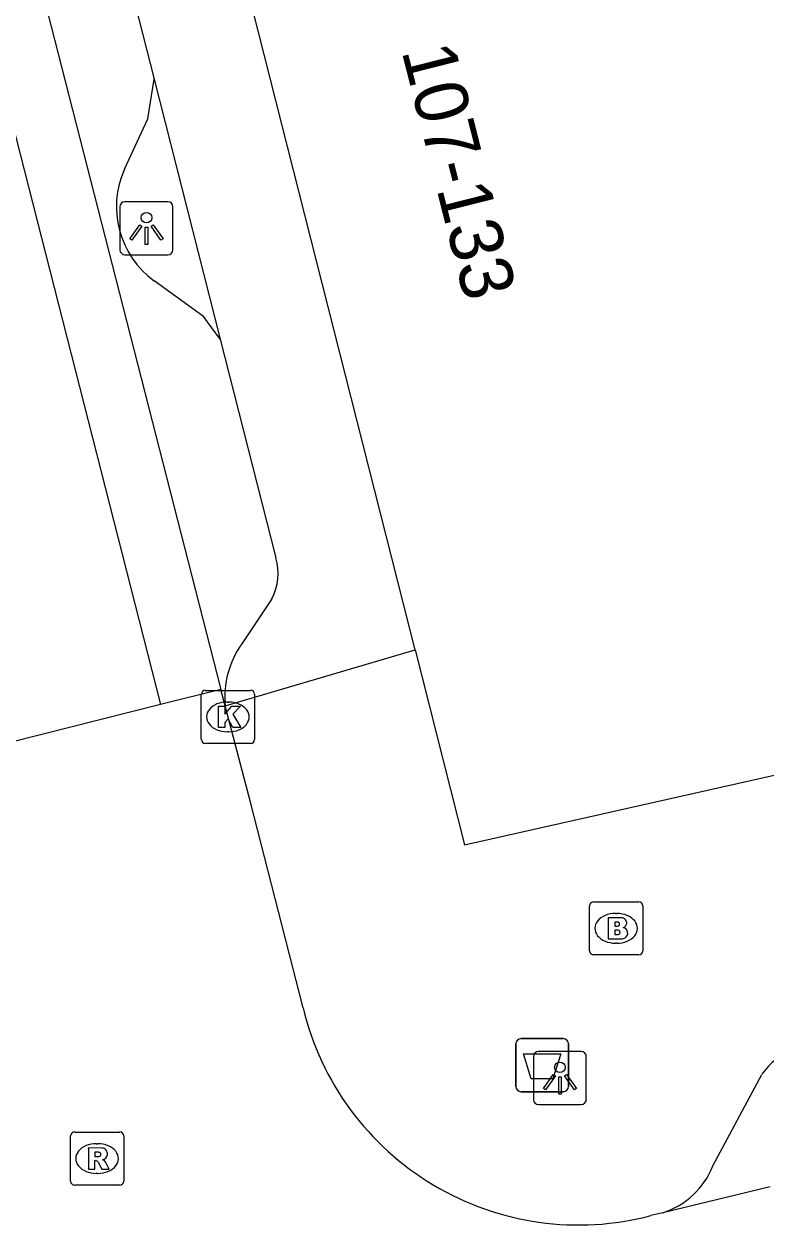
# Model space of a CAD drawing. Extents: x 159265 to 160143, y 383413 to 384319.
# Drawn here: x 159768.06 to 159782.02, y 383626.47 to 383649.08 of the extents above; entities that cross this region are included whole.
import ezdxf

# ---------------------------------------------------------------- set-up
doc = ezdxf.new("R2010")
doc.units = 0
for name, color, linetype in [('IMGEO_Afvalbak', 7, 'Continuous'), ('IMGEO_Brandkraan', 7, 'Continuous'), ('IMGEO_Kolk', 7, 'Continuous'), ('IMGEO_Lichtpunt', 7, 'Continuous'), ('IMGEO_Pand', 7, 'Continuous'), ('IMGEO_Pand_nummerreeks', 7, 'Continuous'), ('IMGEO_Parkeervlak_open', 7, 'Continuous'), ('IMGEO_Rijbaan_lokaal_gesloten', 7, 'Continuous'), ('IMGEO_Rijbaan_lokaal_open', 7, 'Continuous'), ('IMGEO_Rioolput', 7, 'Continuous'), ('IMGEO_Voetpad_open', 7, 'Continuous')]:
    doc.layers.add(name, color=color, linetype=linetype)

msp = doc.modelspace()

# ---------------------------------------------------------------- linework, layer by layer
at = {"layer": 'IMGEO_Afvalbak'}
for p, q in [((159777.316, 383629.077), (159777.316, 383629.877)), ((159777.316, 383629.877), (159777.316, 383629.077)), ((159777.416, 383629.977), (159778.206, 383629.977)), ((159778.206, 383629.977), (159777.416, 383629.977)), ((159778.306, 383629.877), (159778.306, 383629.077)), ((159778.306, 383629.077), (159778.306, 383629.877)), ((159778.206, 383628.977), (159777.416, 383628.977)), ((159777.416, 383628.977), (159778.206, 383628.977))]:
    msp.add_line(p, q, dxfattribs=at)
msp.add_lwpolyline([(159777.459, 383629.691), (159778.163, 383629.691), (159778.014, 383629.221), (159777.608, 383629.221), (159777.459, 383629.691)], dxfattribs=at)
for centre, start, end in [((159777.416, 383629.877), 90, 180), ((159777.416, 383629.877), 90, 180), ((159778.206, 383629.877), 0, 90), ((159778.206, 383629.877), 360, 90), ((159777.416, 383629.077), 180, 270), ((159777.416, 383629.077), 180, 270), ((159778.206, 383629.077), 270, 0), ((159778.206, 383629.077), 270, 0)]:
    msp.add_arc(centre, 0.1, start, end, dxfattribs=at)
at = {"layer": 'IMGEO_Brandkraan'}
for p, q in [((159778.704, 383631.627), (159778.704, 383632.479)), ((159778.779, 383632.553), (159779.631, 383632.553)), ((159779.705, 383632.479), (159779.705, 383631.627)), ((159779.192, 383632.333), (159779.217, 383632.333)), ((159779.215, 383631.773), (159779.19, 383631.773)), ((159779.631, 383631.553), (159778.779, 383631.553))]:
    msp.add_line(p, q, dxfattribs=at)
for points in [[(159778.704, 383631.627), (159778.704, 383632.479)], [(159778.779, 383632.553), (159779.631, 383632.553)], [(159779.705, 383632.479), (159779.705, 383631.627)], [(159779.052, 383632.253), (159779.052, 383631.853), (159779.265, 383631.853)], [(159779.283, 383632.253), (159779.052, 383632.253)], [(159779.231, 383632.172), (159779.177, 383632.172), (159779.177, 383632.096)], [(159779.177, 383632.096), (159779.23, 383632.096)], [(159779.239, 383632.02), (159779.177, 383632.02), (159779.177, 383631.939)], [(159779.177, 383631.939), (159779.239, 383631.939)], [(159779.631, 383631.553), (159778.779, 383631.553)]]:
    msp.add_lwpolyline(points, dxfattribs=at)
for centre, radius, start, end in [((159778.781, 383632.477), 0.0765, 91.552, 178.448), ((159778.781, 383632.477), 0.0765, 91.552, 178.448), ((159779.629, 383632.477), 0.0765, 1.552, 88.448), ((159779.629, 383632.477), 0.0765, 1.552, 88.448), ((159779.232, 383632.134), 0.0379, 267.8285, 90.9355), ((159779.287, 383632.108), 0.145, 59.4692, 91.5367), ((159779.312, 383632.155), 0.0922, 285.5137, 58.1501), ((159779.24, 383631.979), 0.0404, 269.8759, 90.5077), ((159779.317, 383631.963), 0.105, 301.3115, 78.989), ((159779.271, 383632.104), 0.251, 268.6676, 293.5347), ((159778.781, 383631.629), 0.0765, 181.552, 268.448), ((159778.781, 383631.629), 0.0765, 181.552, 268.448), ((159779.629, 383631.629), 0.0765, 271.552, 358.448), ((159779.629, 383631.629), 0.0765, 271.552, 358.448)]:
    msp.add_arc(centre, radius, start, end, dxfattribs=at)
for centre, major_axis, ratio, start_param, end_param in [((159779.191, 383632.053), (-0.387, 0.002), 0.722429, 4.712389, 7.853982), ((159779.216, 383632.053), (-0.39, 0.002), 0.717154, 1.570796, 4.712389)]:
    msp.add_ellipse(centre, major_axis=major_axis, ratio=ratio, start_param=start_param, end_param=end_param, dxfattribs=at)
at = {"layer": 'IMGEO_Kolk'}
for p, q in [((159771.397, 383635.607), (159771.397, 383636.459)), ((159771.472, 383636.533), (159772.324, 383636.533)), ((159772.398, 383636.459), (159772.398, 383635.607)), ((159771.885, 383636.313), (159771.91, 383636.313)), ((159771.908, 383635.753), (159771.883, 383635.753)), ((159772.324, 383635.533), (159771.472, 383635.533))]:
    msp.add_line(p, q, dxfattribs=at)
for points in [[(159771.397, 383635.607), (159771.397, 383636.459)], [(159771.472, 383636.533), (159772.324, 383636.533)], [(159772.398, 383636.459), (159772.398, 383635.607)], [(159771.718, 383636.233), (159771.841, 383636.233), (159771.841, 383636.082), (159771.971, 383636.233), (159772.135, 383636.233), (159771.989, 383636.082), (159772.142, 383635.833), (159771.99, 383635.833), (159771.905, 383635.997), (159771.841, 383635.93), (159771.841, 383635.833), (159771.718, 383635.833), (159771.718, 383636.233)], [(159772.324, 383635.533), (159771.472, 383635.533)]]:
    msp.add_lwpolyline(points, dxfattribs=at)
for centre, start, end in [((159771.474, 383636.457), 91.552, 178.448), ((159771.474, 383636.457), 91.552, 178.448), ((159772.322, 383636.457), 1.552, 88.448), ((159772.322, 383636.457), 1.552, 88.448), ((159771.474, 383635.609), 181.552, 268.448), ((159771.474, 383635.609), 181.552, 268.448), ((159772.322, 383635.609), 271.552, 358.448), ((159772.322, 383635.609), 271.552, 358.448)]:
    msp.add_arc(centre, 0.0765, start, end, dxfattribs=at)
for centre, major_axis, ratio, start_param, end_param in [((159771.884, 383636.033), (-0.387, 0.002), 0.722429, 4.712389, 7.853982), ((159771.909, 383636.033), (-0.39, 0.002), 0.717154, 1.570796, 4.712389)]:
    msp.add_ellipse(centre, major_axis=major_axis, ratio=ratio, start_param=start_param, end_param=end_param, dxfattribs=at)
at = {"layer": 'IMGEO_Lichtpunt'}
for p, q in [((159770.768, 383645.729), (159769.96, 383645.729)), ((159770.768, 383645.729), (159769.96, 383645.729)), ((159769.866, 383645.634), (159769.866, 383644.827)), ((159769.866, 383645.634), (159769.866, 383644.827)), ((159770.862, 383644.827), (159770.862, 383645.634)), ((159770.862, 383644.827), (159770.862, 383645.634)), ((159769.96, 383644.733), (159770.768, 383644.733)), ((159769.96, 383644.733), (159770.768, 383644.733)), ((159777.647, 383629.639), (159777.647, 383628.832)), ((159777.647, 383629.639), (159777.647, 383628.832)), ((159778.549, 383629.734), (159777.741, 383629.734)), ((159778.549, 383629.734), (159777.741, 383629.734)), ((159778.643, 383628.832), (159778.643, 383629.639)), ((159778.643, 383628.832), (159778.643, 383629.639)), ((159777.741, 383628.738), (159778.549, 383628.738)), ((159777.741, 383628.738), (159778.549, 383628.738))]:
    msp.add_line(p, q, dxfattribs=at)
for points in [[(159770.24, 383645.298), (159770.279, 383645.27), (159770.091, 383645.008), (159770.053, 383645.035), (159770.24, 383645.298)], [(159770.342, 383645.25), (159770.389, 383645.25), (159770.389, 383644.928), (159770.342, 383644.928), (159770.342, 383645.25)], [(159770.452, 383645.27), (159770.49, 383645.297), (159770.677, 383645.035), (159770.638, 383645.007), (159770.452, 383645.27)], [(159778.021, 383629.303), (159778.06, 383629.275), (159777.872, 383629.013), (159777.834, 383629.04), (159778.021, 383629.303)], [(159778.123, 383629.255), (159778.17, 383629.255), (159778.17, 383628.933), (159778.123, 383628.933), (159778.123, 383629.255)], [(159778.233, 383629.275), (159778.271, 383629.302), (159778.458, 383629.04), (159778.419, 383629.012), (159778.233, 383629.275)]]:
    msp.add_lwpolyline(points, dxfattribs=at)
for centre in [(159770.365, 383645.432), (159778.146, 383629.437)]:
    msp.add_circle(centre, 0.0994, dxfattribs=at)
for centre, start, end in [((159769.96, 383645.634), 90, 180), ((159769.96, 383645.634), 90, 180), ((159770.768, 383645.634), 0, 90), ((159770.768, 383645.634), 0, 90), ((159769.96, 383644.827), 180, 270), ((159769.96, 383644.827), 180, 270), ((159770.768, 383644.827), 270, 0), ((159770.768, 383644.827), 270, 360), ((159777.741, 383629.639), 90, 180), ((159777.741, 383629.639), 90, 180), ((159778.549, 383629.639), 0, 90), ((159778.549, 383629.639), 0, 90), ((159777.741, 383628.832), 180, 270), ((159777.741, 383628.832), 180, 270), ((159778.549, 383628.832), 270, 0), ((159778.549, 383628.832), 270, 360)]:
    msp.add_arc(centre, 0.0946, start, end, dxfattribs=at)
at = {"layer": 'IMGEO_Pand'}
for points in [[(159775.422, 383637.296), (159771.708, 383651.949)], [(159775.422, 383637.296), (159776.351, 383633.628), (159796.014, 383638.046), (159801.953, 383639.551)]]:
    msp.add_lwpolyline(points, dxfattribs=at)
at = {"layer": 'IMGEO_Parkeervlak_open'}
for points in [[(159769.95, 383646.343), (159770.388, 383647.293), (159770.512, 383648.036)], [(159771.753, 383643.142), (159771.441, 383643.569), (159770.51, 383644.242)]]:
    msp.add_lwpolyline(points, dxfattribs=at)
msp.add_arc((159771.523, 383645.637), 1.724, 155.8259, 234.0233, dxfattribs=at)
at = {"layer": 'IMGEO_Rijbaan_lokaal_gesloten'}
for points in [[(159731.232, 383789.416), (159737.188, 383767.754), (159743.907, 383742.981), (159746.275, 383733.718), (159748.213, 383725.748), (159750.495, 383715.537), (159753.984, 383701.318), (159755.061, 383696.881), (159757.859, 383686.497), (159761.779, 383670.729), (159766.86, 383651.04), (159770.63, 383636.264)], [(159763.044, 383670.613), (159771.767, 383636.551)], [(159771.767, 383636.551), (159770.63, 383636.264)], [(159770.63, 383636.264), (159766.651, 383635.26)]]:
    msp.add_lwpolyline(points, dxfattribs=at)
at = {"layer": 'IMGEO_Rijbaan_lokaal_open'}
for points in [[(159771.848, 383636.241), (159771.767, 383636.551)], [(159773.311, 383630.554), (159772.322, 383634.428), (159771.848, 383636.241)], [(159782.101, 383627.188), (159780.084, 383626.699)], [(159780.084, 383626.699), (159779.858, 383626.645)]]:
    msp.add_lwpolyline(points, dxfattribs=at)
msp.add_arc((159778.498, 383631.804), 5.335, 193.5514, 284.7685, dxfattribs=at)
at = {"layer": 'IMGEO_Rioolput'}
for p, q in [((159768.935, 383627.293), (159768.935, 383628.145)), ((159769.01, 383628.219), (159769.862, 383628.219)), ((159769.936, 383628.145), (159769.936, 383627.293)), ((159769.423, 383627.999), (159769.448, 383627.999)), ((159769.446, 383627.439), (159769.421, 383627.439)), ((159769.862, 383627.219), (159769.01, 383627.219))]:
    msp.add_line(p, q, dxfattribs=at)
for points in [[(159768.935, 383627.293), (159768.935, 383628.145)], [(159769.01, 383628.219), (159769.862, 383628.219)], [(159769.936, 383628.145), (159769.936, 383627.293)], [(159769.524, 383627.917), (159769.272, 383627.919), (159769.272, 383627.519)], [(159769.45, 383627.838), (159769.396, 383627.838), (159769.396, 383627.757)], [(159769.272, 383627.519), (159769.396, 383627.519), (159769.396, 383627.681), (159769.407, 383627.681)], [(159769.396, 383627.757), (159769.448, 383627.757)], [(159769.454, 383627.652), (159769.525, 383627.519), (159769.665, 383627.519), (159769.6, 383627.645)], [(159769.862, 383627.219), (159769.01, 383627.219)]]:
    msp.add_lwpolyline(points, dxfattribs=at)
for centre, radius, start, end in [((159769.012, 383628.143), 0.0765, 91.552, 178.448), ((159769.012, 383628.143), 0.0765, 91.552, 178.448), ((159769.86, 383628.143), 0.0765, 1.552, 88.448), ((159769.86, 383628.143), 0.0765, 1.552, 88.448), ((159769.456, 383627.742), 0.0964, 77.0061, 93.1865), ((159769.47, 383627.799), 0.0378, 276.6634, 79.6772), ((159769.523, 383627.807), 0.109, 350.3612, 89.416), ((159769.406, 383627.628), 0.0533, 26.0293, 88.6989), ((159769.432, 383627.946), 0.19, 274.7715, 282.9687), ((159769.521, 383627.807), 0.112, 277.5842, 350.9817), ((159769.505, 383627.592), 0.108, 29.5134, 73.7905), ((159769.012, 383627.295), 0.0765, 181.552, 268.448), ((159769.012, 383627.295), 0.0765, 181.552, 268.448), ((159769.86, 383627.295), 0.0765, 271.552, 358.448), ((159769.86, 383627.295), 0.0765, 271.552, 358.448)]:
    msp.add_arc(centre, radius, start, end, dxfattribs=at)
for centre, major_axis, ratio, start_param, end_param in [((159769.422, 383627.719), (-0.387, 0.002), 0.722429, 4.712389, 7.853982), ((159769.447, 383627.719), (-0.39, 0.002), 0.717154, 1.570796, 4.712389)]:
    msp.add_ellipse(centre, major_axis=major_axis, ratio=ratio, start_param=start_param, end_param=end_param, dxfattribs=at)
at = {"layer": 'IMGEO_Voetpad_open'}
for points in [[(159763.913, 383669.587), (159764.799, 383669.073), (159765.284, 383668.474), (159770.512, 383648.036)], [(159770.512, 383648.036), (159771.753, 383643.142)], [(159771.753, 383643.142), (159772.802, 383639.026)], [(159772.724, 383638.258), (159772.158, 383637.409)], [(159771.848, 383636.241), (159775.422, 383637.296)], [(159781.026, 383627.585), (159781.947, 383629.304)]]:
    msp.add_lwpolyline(points, dxfattribs=at)
for centre, radius, start, end in [((159771.822, 383638.738), 1.021, 331.9998, 16.4017), ((159773.589, 383636.404), 1.749, 144.922, 185.3495), ((159782.887, 383628.667), 1.136, 106.1957, 145.8481), ((159779.612, 383628.145), 1.521, 288.0824, 338.4082)]:
    msp.add_arc(centre, radius, start, end, dxfattribs=at)

# ---------------------------------------------------------------- texts
at = {"layer": 'IMGEO_Pand_nummerreeks'}
msp.add_text('107-133', height=1, rotation=284.2206, dxfattribs=at).set_placement((159775.163, 383648.573))

doc.saveas('drawing.dxf')
